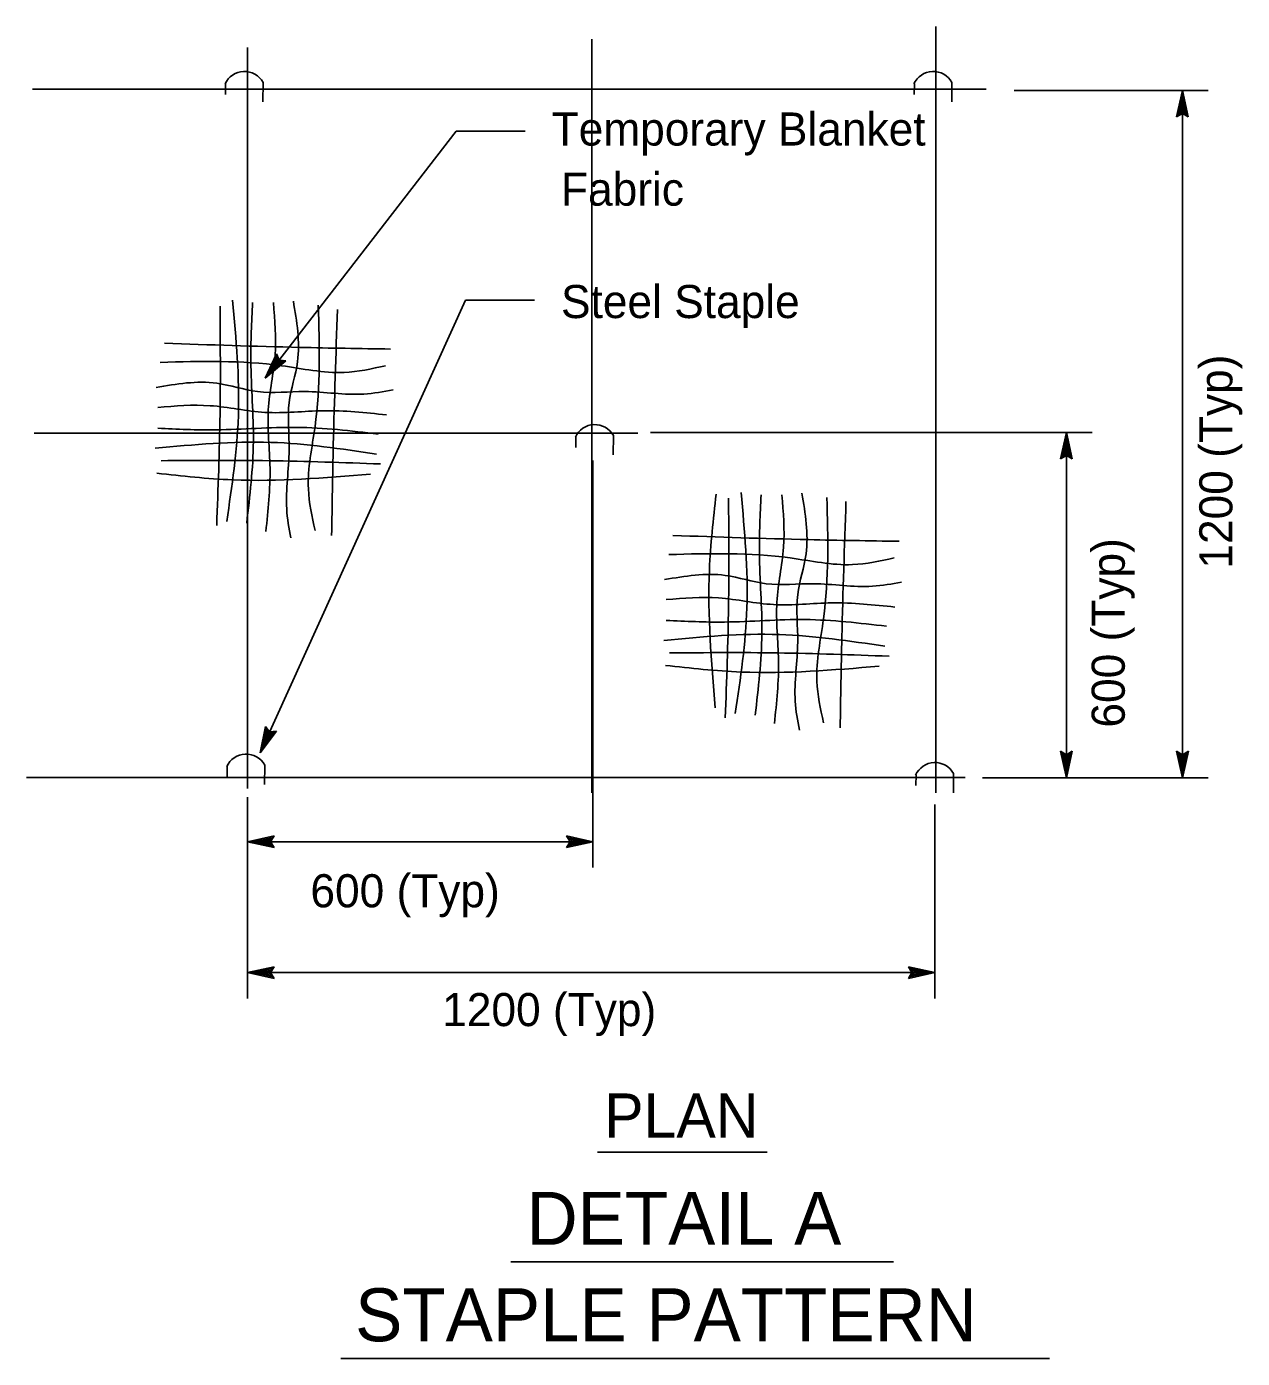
# Model space of a CAD drawing. Extents: x 6712486 to 6713732, y 1869200 to 1869925.
# Drawn here: x 6712486.3 to 6712715.7, y 1869673.5 to 1869924.8 of the extents above; entities that cross this region are included whole.
import ezdxf

# ---------------------------------------------------------------- set-up
doc = ezdxf.new("R2010")
doc.units = 0
for name, color, linetype in [('56 Stg 3 Anno', 7, 'Continuous'), ('57 Undefined', 7, 'Continuous'), ('60 Nongeo Data', 7, 'Continuous')]:
    doc.layers.add(name, color=color, linetype=linetype)

msp = doc.modelspace()

# ---------------------------------------------------------------- linework, layer by layer
at = {"layer": '56 Stg 3 Anno'}
for p, q in [((6712703.27, 1869907.72), (6712704.38, 1869912.72)), ((6712703.57, 1869907.9), (6712704.38, 1869911.57)), ((6712703.86, 1869908.1), (6712704.38, 1869910.42)), ((6712704.38, 1869912.72), (6712704.38, 1869912.72)), ((6712704.38, 1869912.72), (6712705.49, 1869907.72)), ((6712704.38, 1869910.42), (6712704.9, 1869908.07)), ((6712704.39, 1869911.56), (6712705.19, 1869907.92)), ((6712704.38, 1869908.39), (6712703.27, 1869907.72)), ((6712704.15, 1869908.25), (6712704.38, 1869909.27)), ((6712704.38, 1869909.27), (6712704.61, 1869908.26)), ((6712705.49, 1869907.72), (6712704.38, 1869908.39)), ((6712703.27, 1869907.72), (6712703.27, 1869907.72)), ((6712705.49, 1869907.72), (6712705.49, 1869907.72)), ((6712531.31, 1869858.42), (6712533.47, 1869863.06)), ((6712532.02, 1869859.34), (6712533.58, 1869862.72)), ((6712533.47, 1869863.06), (6712533.47, 1869863.06)), ((6712533.47, 1869863.06), (6712533.94, 1869861.86)), ((6712535.23, 1869861.71), (6712531.31, 1869858.42)), ((6712534.89, 1869861.75), (6712532.01, 1869859.33)), ((6712532.71, 1869860.24), (6712533.72, 1869862.43)), ((6712534.53, 1869861.77), (6712532.71, 1869860.24)), ((6712533.41, 1869861.16), (6712533.84, 1869862.09)), ((6712534.21, 1869861.83), (6712533.41, 1869861.16)), ((6712533.94, 1869861.86), (6712535.23, 1869861.71)), ((6712535.23, 1869861.71), (6712535.23, 1869861.71)), ((6712531.31, 1869858.42), (6712531.31, 1869858.42)), ((6712681.36, 1869843.21), (6712682.48, 1869848.2)), ((6712682.48, 1869848.2), (6712682.48, 1869848.2)), ((6712682.48, 1869848.2), (6712683.58, 1869843.21)), ((6712681.66, 1869843.39), (6712682.47, 1869847.05)), ((6712681.96, 1869843.58), (6712682.47, 1869845.9)), ((6712682.47, 1869845.9), (6712682.99, 1869843.55)), ((6712682.48, 1869847.04), (6712683.28, 1869843.4)), ((6712682.48, 1869843.87), (6712681.36, 1869843.21)), ((6712681.36, 1869843.21), (6712681.36, 1869843.21)), ((6712682.24, 1869843.73), (6712682.47, 1869844.75)), ((6712682.47, 1869844.75), (6712682.7, 1869843.75)), ((6712683.58, 1869843.21), (6712682.48, 1869843.87)), ((6712683.58, 1869843.21), (6712683.58, 1869843.21)), ((6712530.34, 1869787.74), (6712531.39, 1869792.75)), ((6712530.81, 1869788.8), (6712531.58, 1869792.45)), ((6712531.39, 1869792.75), (6712531.39, 1869792.75)), ((6712531.39, 1869792.75), (6712532.13, 1869791.69)), ((6712533.42, 1869791.83), (6712530.34, 1869787.74)), ((6712533.07, 1869791.79), (6712530.81, 1869788.79)), ((6712531.29, 1869789.84), (6712531.79, 1869792.19)), ((6712532.72, 1869791.74), (6712531.29, 1869789.84)), ((6712531.76, 1869790.88), (6712531.98, 1869791.89)), ((6712532.4, 1869791.72), (6712531.76, 1869790.88)), ((6712532.13, 1869791.69), (6712533.42, 1869791.83)), ((6712533.42, 1869791.83), (6712533.42, 1869791.83)), ((6712530.34, 1869787.74), (6712530.34, 1869787.74)), ((6712682.48, 1869783.05), (6712681.37, 1869788.04)), ((6712681.37, 1869788.04), (6712681.37, 1869788.04)), ((6712681.37, 1869788.04), (6712682.48, 1869787.38)), ((6712682.47, 1869784.21), (6712681.67, 1869787.85)), ((6712682.48, 1869785.35), (6712681.96, 1869787.7)), ((6712682.48, 1869786.5), (6712682.25, 1869787.5)), ((6712682.48, 1869787.38), (6712683.59, 1869788.04)), ((6712683.59, 1869788.04), (6712682.48, 1869783.05)), ((6712683.29, 1869787.86), (6712682.48, 1869784.2)), ((6712683, 1869787.67), (6712682.48, 1869785.35)), ((6712682.71, 1869787.52), (6712682.48, 1869786.5)), ((6712683.59, 1869788.04), (6712683.59, 1869788.04)), ((6712704.38, 1869783.05), (6712703.28, 1869788.04)), ((6712703.28, 1869788.04), (6712703.28, 1869788.04)), ((6712703.28, 1869788.04), (6712704.38, 1869787.38)), ((6712704.38, 1869784.21), (6712703.58, 1869787.85)), ((6712704.39, 1869785.35), (6712703.87, 1869787.7)), ((6712704.39, 1869786.5), (6712704.16, 1869787.5)), ((6712704.38, 1869787.38), (6712705.5, 1869788.04)), ((6712705.5, 1869788.04), (6712704.38, 1869783.05)), ((6712705.2, 1869787.86), (6712704.39, 1869784.2)), ((6712704.9, 1869787.67), (6712704.39, 1869785.35)), ((6712704.62, 1869787.52), (6712704.39, 1869786.5)), ((6712705.5, 1869788.04), (6712705.5, 1869788.04)), ((6712682.48, 1869783.05), (6712682.48, 1869783.05)), ((6712704.38, 1869783.05), (6712704.38, 1869783.05)), ((6712528, 1869770.99), (6712533, 1869772.1)), ((6712533, 1869769.87), (6712528, 1869770.99)), ((6712528, 1869770.99), (6712528, 1869770.99)), ((6712532.82, 1869770.17), (6712529.15, 1869770.99)), ((6712529.16, 1869770.99), (6712532.8, 1869771.8)), ((6712530.3, 1869770.99), (6712532.66, 1869771.51)), ((6712532.62, 1869770.47), (6712530.3, 1869770.99)), ((6712531.45, 1869770.99), (6712532.46, 1869771.21)), ((6712532.48, 1869770.76), (6712531.45, 1869770.99)), ((6712533, 1869772.1), (6712532.33, 1869770.99)), ((6712532.33, 1869770.99), (6712533, 1869769.87)), ((6712533, 1869772.1), (6712533, 1869772.1)), ((6712533, 1869769.87), (6712533, 1869769.87)), ((6712588.83, 1869770.99), (6712588.16, 1869772.1)), ((6712588.16, 1869772.1), (6712588.16, 1869772.1)), ((6712588.16, 1869772.1), (6712593.16, 1869770.99)), ((6712593.16, 1869770.99), (6712588.16, 1869769.88)), ((6712588.16, 1869769.88), (6712588.83, 1869770.99)), ((6712588.16, 1869769.88), (6712588.16, 1869769.88)), ((6712588.34, 1869771.81), (6712592.01, 1869770.99)), ((6712592, 1869770.99), (6712588.36, 1869770.18)), ((6712590.86, 1869770.99), (6712588.51, 1869770.47)), ((6712588.54, 1869771.51), (6712590.86, 1869770.99)), ((6712588.69, 1869771.22), (6712589.71, 1869770.99)), ((6712589.71, 1869770.99), (6712588.7, 1869770.77)), ((6712593.16, 1869770.99), (6712593.16, 1869770.99)), ((6712528, 1869746.29), (6712533, 1869747.4)), ((6712529.16, 1869746.3), (6712532.8, 1869747.1)), ((6712533, 1869747.4), (6712532.33, 1869746.29)), ((6712533, 1869747.4), (6712533, 1869747.4)), ((6712653.35, 1869746.29), (6712652.68, 1869747.41)), ((6712652.68, 1869747.41), (6712652.68, 1869747.41)), ((6712652.68, 1869747.41), (6712657.68, 1869746.29)), ((6712652.86, 1869747.11), (6712656.53, 1869746.29)), ((6712533, 1869745.18), (6712528, 1869746.29)), ((6712528, 1869746.29), (6712528, 1869746.29)), ((6712532.82, 1869745.47), (6712529.15, 1869746.29)), ((6712530.3, 1869746.29), (6712532.66, 1869746.81)), ((6712532.62, 1869745.77), (6712530.3, 1869746.29)), ((6712531.45, 1869746.29), (6712532.46, 1869746.51)), ((6712532.48, 1869746.06), (6712531.45, 1869746.29)), ((6712532.33, 1869746.29), (6712533, 1869745.18)), ((6712533, 1869745.18), (6712533, 1869745.18)), ((6712657.68, 1869746.29), (6712652.68, 1869745.19)), ((6712652.68, 1869745.19), (6712653.35, 1869746.29)), ((6712652.68, 1869745.19), (6712652.68, 1869745.19)), ((6712656.52, 1869746.29), (6712652.88, 1869745.48)), ((6712655.38, 1869746.29), (6712653.02, 1869745.77)), ((6712653.06, 1869746.81), (6712655.38, 1869746.29)), ((6712653.2, 1869746.52), (6712654.23, 1869746.3)), ((6712654.23, 1869746.3), (6712653.22, 1869746.07)), ((6712657.68, 1869746.29), (6712657.68, 1869746.29))]:
    msp.add_line(p, q, dxfattribs=at)
at = {"layer": '57 Undefined'}
for p, q in [((6712593.99, 1869712.38), (6712626.04, 1869712.38)), ((6712577.67, 1869691.71), (6712649.86, 1869691.71)), ((6712545.61, 1869673.51), (6712679.32, 1869673.51))]:
    msp.add_line(p, q, dxfattribs=at)
at = {"layer": '60 Nongeo Data'}
for p, q in [((6712657.87, 1869924.77), (6712657.87, 1869780.18)), ((6712527.97, 1869920.83), (6712527.97, 1869781.04)), ((6712592.92, 1869922.43), (6712592.92, 1869780.18)), ((6712487.37, 1869912.99), (6712667.33, 1869912.99)), ((6712523.83, 1869914), (6712523.75, 1869913.95)), ((6712523.81, 1869911.98), (6712523.83, 1869914)), ((6712530.91, 1869914.25), (6712530.88, 1869910.6)), ((6712530.91, 1869914.25), (6712530.91, 1869914.25)), ((6712653.8, 1869914), (6712653.72, 1869913.95)), ((6712653.78, 1869911.98), (6712653.8, 1869914)), ((6712660.88, 1869914.25), (6712660.85, 1869910.6)), ((6712660.88, 1869914.25), (6712660.88, 1869914.25)), ((6712672.66, 1869912.72), (6712709.26, 1869912.72)), ((6712704.38, 1869783.05), (6712704.38, 1869912.72)), ((6712531.31, 1869858.42), (6712567.36, 1869905.06)), ((6712580.35, 1869905.06), (6712567.36, 1869905.06)), ((6712530.34, 1869787.74), (6712569.13, 1869873.18)), ((6712582.12, 1869873.18), (6712569.13, 1869873.18)), ((6712487.72, 1869848.05), (6712601.61, 1869848.05)), ((6712597.01, 1869847.61), (6712596.99, 1869843.96)), ((6712597.01, 1869847.61), (6712597.01, 1869847.61)), ((6712604.01, 1869848.2), (6712687.35, 1869848.2)), ((6712682.48, 1869783.05), (6712682.48, 1869848.2)), ((6712589.93, 1869847.36), (6712589.85, 1869847.32)), ((6712589.92, 1869845.34), (6712589.93, 1869847.36)), ((6712593.16, 1869842.94), (6712593.16, 1869766.12)), ((6712524.15, 1869785.19), (6712524.06, 1869785.14)), ((6712524.13, 1869783.17), (6712524.15, 1869785.19)), ((6712531.23, 1869785.44), (6712531.2, 1869781.79)), ((6712531.23, 1869785.44), (6712531.23, 1869785.44)), ((6712486.29, 1869783.1), (6712663.4, 1869783.1)), ((6712654.12, 1869783.59), (6712654.03, 1869783.55)), ((6712654.1, 1869781.58), (6712654.12, 1869783.59)), ((6712661.2, 1869783.85), (6712661.17, 1869780.2)), ((6712661.2, 1869783.85), (6712661.2, 1869783.85)), ((6712666.68, 1869783.05), (6712709.26, 1869783.05)), ((6712528, 1869779.37), (6712528, 1869741.42)), ((6712657.68, 1869778.02), (6712657.68, 1869741.42)), ((6712528, 1869770.99), (6712593.16, 1869770.99)), ((6712528, 1869746.29), (6712657.68, 1869746.29))]:
    msp.add_line(p, q, dxfattribs=at)
for centre in [(6712527.4, 1869912.31), (6712657.37, 1869912.31), (6712593.5, 1869845.68), (6712527.72, 1869783.51), (6712657.69, 1869781.91)]:
    msp.add_arc(centre, 4.01, 28.8752, 155.8761, dxfattribs=at)
for points in [[(6712525.15, 1869873.16), (6712526.25, 1869851.35), (6712524.05, 1869831.43)], [(6712528.92, 1869872.69), (6712528.6, 1869861.71), (6712529.08, 1869846.49), (6712527.82, 1869831.11)], [(6712532.85, 1869872.69), (6712533.16, 1869862.8), (6712531.9, 1869852.45), (6712532.22, 1869841.47), (6712531.43, 1869829.54)], [(6712536.62, 1869873), (6712537.41, 1869861.55), (6712535.83, 1869853.86), (6712535.83, 1869844.92), (6712535.36, 1869833.78), (6712536.15, 1869828.29)], [(6712522.16, 1869830.64), (6712522.79, 1869851.67), (6712522.79, 1869872.06)], [(6712541.33, 1869872.22), (6712540.71, 1869849.31), (6712539.45, 1869837.54), (6712540.71, 1869829.7)], [(6712544.95, 1869871.43), (6712544.16, 1869845.86), (6712543.85, 1869828.76)], [(6712512.29, 1869865.03), (6712537.86, 1869864.25), (6712554.96, 1869863.93)], [(6712511.5, 1869861.42), (6712534.41, 1869860.79), (6712546.18, 1869859.53), (6712554.02, 1869860.79)], [(6712510.72, 1869856.7), (6712522.17, 1869857.49), (6712529.86, 1869855.92), (6712538.8, 1869855.92), (6712549.94, 1869855.45), (6712555.44, 1869856.23)], [(6712511.03, 1869852.93), (6712520.92, 1869853.25), (6712531.27, 1869851.99), (6712542.26, 1869852.3), (6712554.18, 1869851.52)], [(6712511.03, 1869849), (6712522.02, 1869848.69), (6712537.24, 1869849.16), (6712552.61, 1869847.9)], [(6712510.56, 1869845.23), (6712532.37, 1869846.33), (6712552.3, 1869844.13)], [(6712553.08, 1869842.25), (6712532.06, 1869842.87), (6712511.66, 1869842.87)], [(6712551.2, 1869840.36), (6712525.15, 1869839.26), (6712510.88, 1869840.52)], [(6712616.23, 1869796.26), (6712615.13, 1869822.31), (6712616.39, 1869836.58)], [(6712618.12, 1869794.38), (6712618.74, 1869815.4), (6712618.74, 1869835.8)], [(6712621.1, 1869836.9), (6712622.2, 1869815.09), (6712620, 1869795.16)], [(6712624.87, 1869836.43), (6712624.56, 1869825.44), (6712625.03, 1869810.23), (6712623.77, 1869794.85)], [(6712628.8, 1869836.43), (6712629.12, 1869826.54), (6712627.86, 1869816.19), (6712628.17, 1869805.21), (6712627.39, 1869793.28)], [(6712632.57, 1869836.74), (6712633.36, 1869825.29), (6712631.79, 1869817.6), (6712631.79, 1869808.66), (6712631.32, 1869797.52), (6712632.1, 1869792.03)], [(6712637.29, 1869835.96), (6712636.66, 1869813.05), (6712635.4, 1869801.28), (6712636.66, 1869793.44)], [(6712640.9, 1869835.17), (6712640.12, 1869809.6), (6712639.8, 1869792.5)], [(6712608.24, 1869828.77), (6712633.82, 1869827.98), (6712650.92, 1869827.67)], [(6712607.46, 1869825.16), (6712630.37, 1869824.53), (6712642.13, 1869823.27), (6712649.98, 1869824.53)], [(6712606.67, 1869820.44), (6712618.13, 1869821.23), (6712625.82, 1869819.66), (6712634.76, 1869819.66), (6712645.9, 1869819.18), (6712651.39, 1869819.97)], [(6712606.99, 1869816.67), (6712616.87, 1869816.98), (6712627.23, 1869815.73), (6712638.21, 1869816.04), (6712650.13, 1869815.26)], [(6712606.99, 1869812.74), (6712617.97, 1869812.43), (6712633.19, 1869812.9), (6712648.57, 1869811.64)], [(6712606.52, 1869808.97), (6712628.33, 1869810.07), (6712648.25, 1869807.87)], [(6712649.04, 1869805.98), (6712628.01, 1869806.61), (6712607.62, 1869806.61)], [(6712647.15, 1869804.1), (6712621.11, 1869803), (6712606.83, 1869804.25)]]:
    msp.add_spline(points, degree=3, dxfattribs=at)

# ---------------------------------------------------------------- texts
at = {"layer": '57 Undefined'}
for s, height, p in [('PLAN', 8.327, (6712595.28, 1869715.17)), ('DETAIL A', 9.992, (6712580.62, 1869694.93)), ('STAPLE PATTERN', 9.9921, (6712548.28, 1869676.73))]:
    msp.add_text(s, height=height, dxfattribs=at).set_placement(p)
at = {"layer": '60 Nongeo Data'}
for s, height, p in [('Temporary Blanket', 6.2451, (6712585.36, 1869902.33)), ('Fabric', 6.245, (6712587.12, 1869890.99)), ('Steel Staple', 6.2451, (6712587.13, 1869869.78)), ('600 (Typ)', 6.245, (6712539.84, 1869758.61)), ('1200 (Typ)', 6.245, (6712564.71, 1869736.19))]:
    msp.add_text(s, height=height, dxfattribs=at).set_placement(p)
for s, p in [('1200 (Typ)', (6712713.81, 1869822.51)), ('600 (Typ)', (6712693.5, 1869792.52))]:
    msp.add_text(s, height=6.245, rotation=90, dxfattribs=at).set_placement(p)

doc.saveas('drawing.dxf')
